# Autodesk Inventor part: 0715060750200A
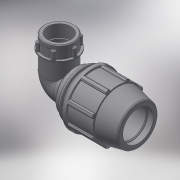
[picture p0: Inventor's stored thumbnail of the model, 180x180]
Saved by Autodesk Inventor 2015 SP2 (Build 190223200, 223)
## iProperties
Created: 2017-02
Part Number: 0715060750200A
Material: Generic
Description: PLASSON 90° ELBOW FEMALE ADAPTOR 75-2"
Document SubType Name: Modeling
Designer: KIM
Mass: 1287.77 g
Surface Area: 1760.4 cm^2
Volume: 1287.77 cm^3
Density: 1 g/cm^3
Appearance: Default
Author: KIM
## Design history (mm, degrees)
derived "87150.ipt"
feature "Solid1::87150.ipt"
tag "TaggingFeature1"
body "Solid1"
other parameters: "d2" = 75, "d4" = 15.66667, "d5" = 47, "d7" = 134, "d9" = 26.85714, "d11" = 6.26667, "d13" = 120 deg, "d14" = 97.5, "d15" = 12 deg, "d16" = 116.58, "d18" = 3.75, "d19" = 35 deg, "d20" = 17.5 deg, "d21" = 124.62, "d23" = 0, "d25" = 360 deg, "d27" = 2.68, "d33" = 1.5, "d42" = 69.56, "d43" = 4.02, "d46" = 2.25, "d51" = 188, "d68" = 12.53333, "d73" = 73.6528, "d75" = 84.70072, "d76" = 56.656, "d77" = 33, "d79" = 22.6624, "d80" = 1.69968, "d83" = 0, "d84" = 0, "d91" = 100.5, "d93" = 132, "d94" = 56.656, "d95" = 39.6592, "d96" = 12.53333, "d97" = 50 deg, "d98" = 50.9904, "d99" = 0.5, "d100" = 0.5, "d101" = 10, "d102" = 73.6528, "d103" = 25.8, "d104" = 0, "d108" = 360 deg, "d110" = 2.20958, "d111" = 8.93333, "d112" = 0, "d113" = 3.13333, "d114" = 3.13333, "d115" = 113.0826, "d_" = 75, "E_" = 134, "A_" = 188, "l_" = 132, "Rp_" = 56.656, "d105" = 11.04792
